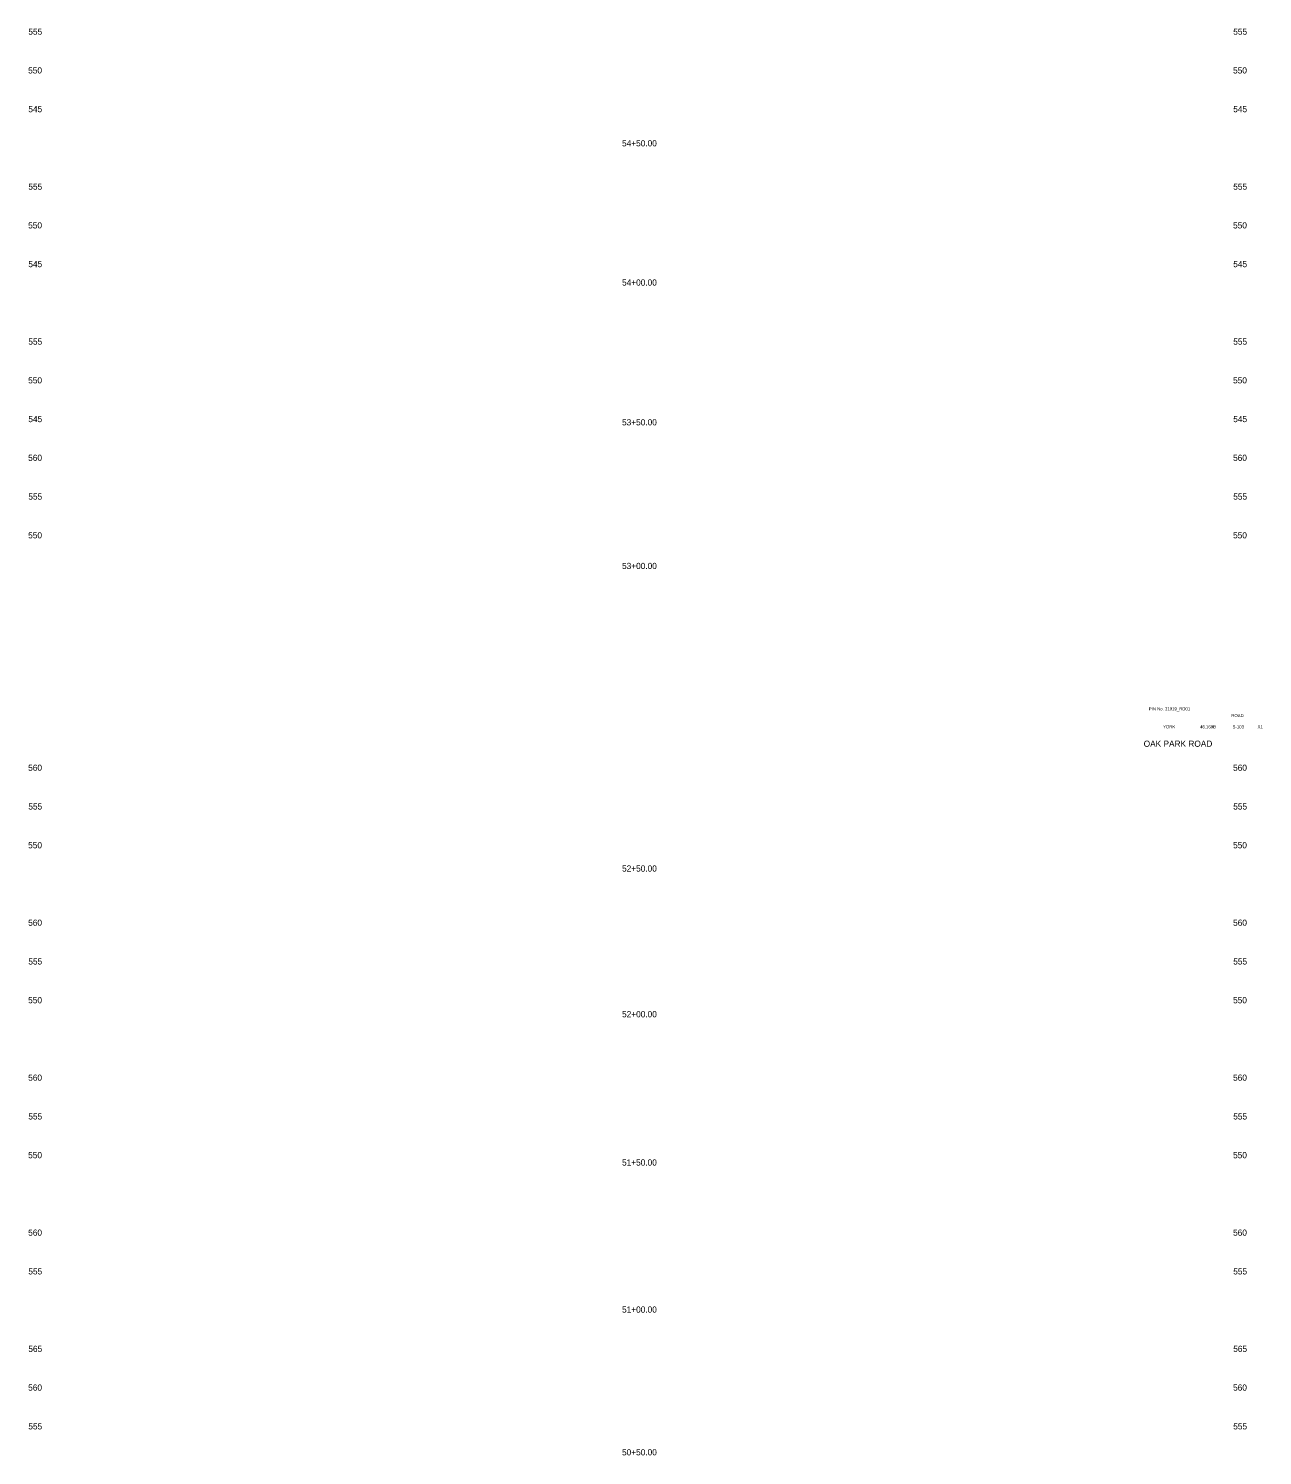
# Model space of a CAD drawing. Extents: x 1001 to 1161, y 1007 to 2483.
# Drawn here: x 1001.2 to 1160.4, y 1006.6 to 1190.8 of the extents above; entities that cross this region are included whole.
import ezdxf

# ---------------------------------------------------------------- set-up
doc = ezdxf.new("R2010")
doc.units = 0
for name, color, linetype in [('RD_GPK_XS_Cell', 7, 'Continuous'), ('RD_SHT_TX', 7, 'Continuous'), ('RD_XS_ExGround', 7, 'Continuous')]:
    doc.layers.add(name, color=color, linetype=linetype)

msp = doc.modelspace()

# ---------------------------------------------------------------- texts
at = {"layer": 'RD_GPK_XS_Cell'}
for s, p in [('555', (1001.16, 1190)), ('555', (1156.66, 1190)), ('550', (1001.14, 1185)), ('550', (1156.64, 1185)), ('545', (1001.16, 1180)), ('545', (1156.66, 1180)), ('555', (1001.16, 1170)), ('555', (1156.66, 1170)), ('550', (1001.14, 1165)), ('550', (1156.64, 1165)), ('545', (1001.16, 1160)), ('545', (1156.66, 1160)), ('555', (1001.16, 1150)), ('555', (1156.66, 1150)), ('550', (1001.14, 1145)), ('550', (1156.64, 1145)), ('545', (1001.16, 1140)), ('545', (1156.66, 1140)), ('560', (1001.14, 1135)), ('560', (1156.64, 1135)), ('555', (1001.16, 1130)), ('555', (1156.66, 1130)), ('550', (1001.14, 1125)), ('550', (1156.64, 1125)), ('560', (1001.14, 1095)), ('560', (1156.64, 1095)), ('555', (1001.16, 1090)), ('555', (1156.66, 1090)), ('550', (1001.14, 1085)), ('550', (1156.64, 1085)), ('560', (1001.14, 1075)), ('560', (1156.64, 1075)), ('555', (1001.16, 1070)), ('555', (1156.66, 1070)), ('550', (1001.14, 1065)), ('550', (1156.64, 1065)), ('560', (1001.14, 1055)), ('560', (1156.64, 1055)), ('555', (1001.16, 1050)), ('555', (1156.66, 1050)), ('550', (1001.14, 1045)), ('550', (1156.64, 1045)), ('560', (1001.14, 1035)), ('560', (1156.64, 1035)), ('555', (1001.16, 1030)), ('555', (1156.66, 1030)), ('565', (1001.16, 1020)), ('565', (1156.66, 1020)), ('560', (1001.14, 1015)), ('560', (1156.64, 1015)), ('555', (1001.16, 1010)), ('555', (1156.66, 1010))]:
    msp.add_text(s, height=0.8, dxfattribs=at).set_placement(p)
at = {"layer": 'RD_SHT_TX'}
for s, height, p in [('PIN No. 31919_RD01', 0.4, (1145.76, 1102.8)), ('ROAD', 0.4, (1156.41, 1101.93)), ('YORK', 0.4, (1147.61, 1100.48)), ('46.169B', 0.4, (1152.37, 1100.48)), ('S-103', 0.4, (1156.57, 1100.48)), ('X1', 0.4, (1159.8, 1100.48)), ('OAK PARK ROAD', 0.8, (1145.1, 1098.1))]:
    msp.add_text(s, height=height, dxfattribs=at).set_placement(p)
at = {"layer": 'RD_XS_ExGround'}
for s, p in [('54+50.00', (1077.78, 1175.59)), ('54+00.00', (1077.78, 1157.62)), ('53+50.00', (1077.78, 1139.58)), ('53+00.00', (1077.78, 1121.04)), ('52+50.00', (1077.78, 1081.99)), ('52+00.00', (1077.78, 1063.19)), ('51+50.00', (1077.78, 1044.05)), ('51+00.00', (1077.78, 1025.07)), ('50+50.00', (1077.78, 1006.65))]:
    msp.add_text(s, height=0.8, dxfattribs=at).set_placement(p)

doc.saveas('drawing.dxf')
